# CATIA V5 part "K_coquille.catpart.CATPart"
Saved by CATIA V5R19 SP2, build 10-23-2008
Part number: coquille 11
Bounding box of the stored display mesh (mm): x -239.865 to 239.865, y -363 to 200, z -239.865 to 239.865
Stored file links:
  G:\Khaled_CFAO_2011\ST2M\ST2M_GR1\mponsin\Khaled\CAD_ThinkMOTION\K_coquille.catpart.CATPart
  C:\Users\Socar\Documents\thinkmotion\Final\Diff2.CATProduct
  G:\Khaled_CFAO_2011\ST2M\ST2M_GR1\mponsin\Khaled\CAD_ThinkMOTION\K_mponsin.CATProduct
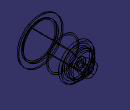
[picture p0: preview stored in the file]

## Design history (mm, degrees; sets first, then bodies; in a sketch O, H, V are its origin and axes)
External parameters (linked from other documents)
  `External.R palier` = 70 mm
  `External.R cardan` = 30 mm
  `External.hauteur du visco` = 170 mm
  `External.R interne` = 160 mm
  External.LongueurPortee = 10 mm
  External.DiamPortee = 80 mm
  External.DiamPied = 270 mm
  External.DiamTete = 288 mm
  `External.diam prim` = 240 mm
  `External.R portée` = 40 mm
  `External.longueur portée` = 3 mm
Set1
  DatumPoint1 to DatumPoint3: linked copy from another document
  Point1 "Origine": linked copy from another document
  Plane1 "interface 11/V": linked copy from another document
  Plane2 "debut": linked copy from another document
  Plane3 "interface visco/embrayage": linked copy from another document
  Line1 "axe general": linked copy from another document
  DatumSurface1: linked copy from another document
  Plane4: linked copy from another document
Body1 (main body)
  Sketch1 on yz-plane, origin (0, 0, 0), H (0, 1, 0), V (0, 0, 1)
    line L1 (200, 30) -> (200, 70)
    line L2 (200, 70) -> (125, 70)
    line L3 (125, 70) -> (125, 120)
    line L4 (125, 120) -> (103, 120)
    line L5 (103, 120) -> (103, 138.2843)
    line L6 (103, 138.2843) -> (60.206, 181.0783)
    line L7 (38.9928, 189.8651) -> (-343, 189.8651)
    line L8 (-343, 189.8651) -> (-343, 239.8651)
    line L9 (-343, 239.8651) -> (-358, 239.8651)
    point P9 (-358, 239.8651)
    line L10 (-358, 239.8651) -> (-358, 189.8651)
    point P10 (-358, 189.8651)
    line L11 (-358, 189.8651) -> (-363, 189.8651)
    point P11 (-363, 189.8651)
    line L12 (-363, 189.8651) -> (-363, 175)
    line L13 (-363, 175) -> (-107, 175)
    point P13 (74.0787, 138.9213)
    line L14 (74.0787, 138.9213) -> (83, 130)
    point P14 (83, 130)
    line L15 (83, 130) -> (83, 60)
    line L16 (83, 60) -> (80, 60)
    line L17 (80, 60) -> (80, 40)
    line L18 (80, 40) -> (83, 40)
    line L19 (83, 40) -> (83, 30)
    line L20 (83, 30) -> (200, 30)
    reference projected point E1 (-358, 189.8651) from DatumPoint1
    reference projected point E2 (-363, 189.8651) from DatumPoint2
    reference projected point E3 (-358, 239.8651) from DatumPoint3
    line L21 (-107, 175) -> (-107, 160)
    line L22 (-107, 160) -> (50, 160)
    reference intersected line E4 through (-110, 0) direction (0, 1) from Plane3
    reference projected point E5 (0, 0) from Point1
    reference intersected line E6 through (83, 0) direction (0, 1) from face of DatumSurface1
    reference intersected line E7 through (200, 0) direction (0, 1) from Plane2
    arc A1 centre (38.9928, 159.8651) radius 30 from (60.206, 181.0783) to (38.9928, 189.8651) ccw
    line L23 (50, 160) -> (50, 138.9213)
    line L24 (50, 138.9213) -> (74.0787, 138.9213)
    point P27 (74.0787, 138.9213)
    reference intersected line E8 through (50, 0) direction (0, 1) from Plane1
    reference intersected line E9 through (0, 138.9213) direction (1, 0) from Plane4
    length L9 = 15
    distance L13 H = 175 {= `External.hauteur du visco` +5mm}
    distance L20 H = 30 {= `External.R cardan`}
    distance L2 H = 70 {= `External.R palier`}
    length L16 = 3
    distance L21 E4 = 3
    distance L22 E5 = 160 {= `External.R interne`}
    length L18 = 3 {= `External.longueur portée`}
    length L17 = 20
    distance P14 H = 130 {= 10mm+`External.diam prim` /2}
    length L2 = 75 {= `External.R palier` +5mm}
    radius A1 = 30
    angle L15 L14 = 135
    distance L5 L15 = 20
    distance L6 L14 = 20
    length L3 = 50
    distance L18 H = 40 {= `External.R portée`}
    vertical: L1 V, L3 V, L5 V, L8 V, L10 V, L12 V, L15 V, L17 V, L19 V, L21 V, L23 V
    horizontal: L2 H, L4 H, L7 H, L9 H, L11 H, L13 H, L16 H, L18 H, L20 H, L22 H, L24 H
    coincidence: P10 L7, E1 P10, E2 P11, E3 P9, L19 E6, L1 E7, L23 E8, P27 P13, L24 E9
    tangency: A1 L6, A1 L7
  Shaft1: profile Sketch1, axis Line1, angle 360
